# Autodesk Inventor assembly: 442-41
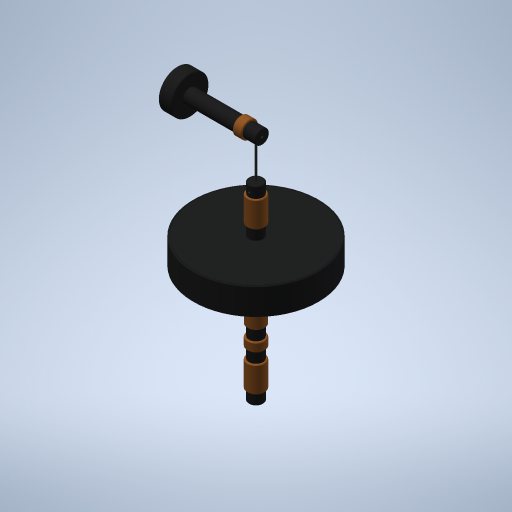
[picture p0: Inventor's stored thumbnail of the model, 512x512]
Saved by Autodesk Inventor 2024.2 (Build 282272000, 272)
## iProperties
Manager: Filip
Company: DARK
Created: 2023-10
Part Number: 442-41
Document SubType Name: Assembly
Designer: Manuel
Engineer: Filip
Project: 442 - TOTM
Description: TOTM Small - Wall
Author: Manuel
Revision Number: v1
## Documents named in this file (13)
- C:\Users\Stage\Desktop\Stage Karsten\armatures\TOTM - Wall\442_KARSTEN\3D_LIB_TOTM_WALL.iam
- C:\Users\Stage\Desktop\Stage Karsten\armatures\TOTM - Wall\442-057.ipt
- C:\Users\Stage\Desktop\Stage Karsten\armatures\TOTM - Wall\Coaxial 2P - TOTM Small Wall.ipt
- C:\Users\Stage\Desktop\Stage Karsten\armatures\TOTM - Wall\442-058.ipt
- C:\Users\Stage\Desktop\Stage Karsten\armatures\TOTM - Wall\442-059.ipt
- N:\LIBRARY\ALLERLEI\190-3000-000137.ipt
- C:\Users\Stage\Desktop\Stage Karsten\armatures\TOTM - Wall\442-060.ipt
- N:\LIBRARY\BEVESTIGING\DIN 916\M4\DIN 916 M4 x 8.ipt
- N:\LIBRARY\BEVESTIGING\DIN 916\M3\DIN 916 M3 x 8.ipt
- C:\Users\Stage\Desktop\Stage Karsten\armatures\TOTM - Wall\442-70.iam
- C:\Users\Stage\Desktop\Stage Barend Nijs\3D\totm\442 - TOTM\442 - TOTM\TOTM - Small\442-083.ipt
- N:\PROJECTS CURRENT\442 - TOTM\Draadstang M10x1 L110.ipt
- C:\Users\Stage\Desktop\Stage Karsten\armatures\TOTM - Wall\442-41.iam
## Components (14 placed, 11 different names)
1. 442-70:1 [sub-assembly] — Flush:1, Mate:6
2. 442-057:1
3. 442-083:1 — Mate:2, Mate:3, Mate:10, Mate:11
4. Draadstang M10x1 L110:1 — Mate:4, Mate:5, Mate:7, Angle:2, Mate:8, Mate:14
5. Coaxial 2P - TOTM Small Wall:1 — Mate:6, Mate:7, Mate:9, Mate:1, Angle:1
6. 442-058:1
7. 442-059:1 — Mate:10, Mate:11, Mate:21
8. 190-3000-000137:1 — Mate:13, Mate:14
9. 442-060:1 — Flush:3, Mate:15, Flush:4
10. DIN 916 M4 x 8:1 — Angle:3, Mate:17
11. DIN 916 M4 x 8:2
12. DIN 916 M3 x 8:1 — Angle:5, Mate:20, Tangent:1
13. DIN 916 M3 x 8:2
14. DIN 916 M3 x 8:3
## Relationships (25: Mate 17, Angle 4, Flush 3, Tangent 1)
- Angle:1: Coaxial 2P - TOTM Small Wall:1
- Mate:1: Coaxial 2P - TOTM Small Wall:1
- Flush:1: 442-70:1
- Mate:2: 442-083:1
- Mate:3: 442-083:1
- Mate:4: Draadstang M10x1 L110:1
- Mate:5: Draadstang M10x1 L110:1
- Mate:6: 442-70:1 ↔ Coaxial 2P - TOTM Small Wall:1
- Mate:7: Draadstang M10x1 L110:1 ↔ Coaxial 2P - TOTM Small Wall:1
- Angle:2: Draadstang M10x1 L110:1
- Mate:8: Draadstang M10x1 L110:1
- Mate:9: Coaxial 2P - TOTM Small Wall:1
- Mate:10: 442-083:1 ↔ 442-059:1
- Mate:11: 442-083:1 ↔ 442-059:1
- Mate:13: 190-3000-000137:1
- Mate:14: Draadstang M10x1 L110:1 ↔ 190-3000-000137:1
- Flush:3: 442-060:1
- Mate:15: 442-060:1
- Flush:4: 442-060:1
- Angle:3: DIN 916 M4 x 8:1
- Mate:17: DIN 916 M4 x 8:1
- Angle:5: DIN 916 M3 x 8:1
- Mate:20: DIN 916 M3 x 8:1
- Tangent:1: DIN 916 M3 x 8:1
- Mate:21: 442-059:1
